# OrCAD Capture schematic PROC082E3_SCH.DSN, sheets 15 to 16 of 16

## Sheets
15 09. FPD LINK_CAM/RDR_IN2: size C; title: FPD Link Camera/RADAR Input2
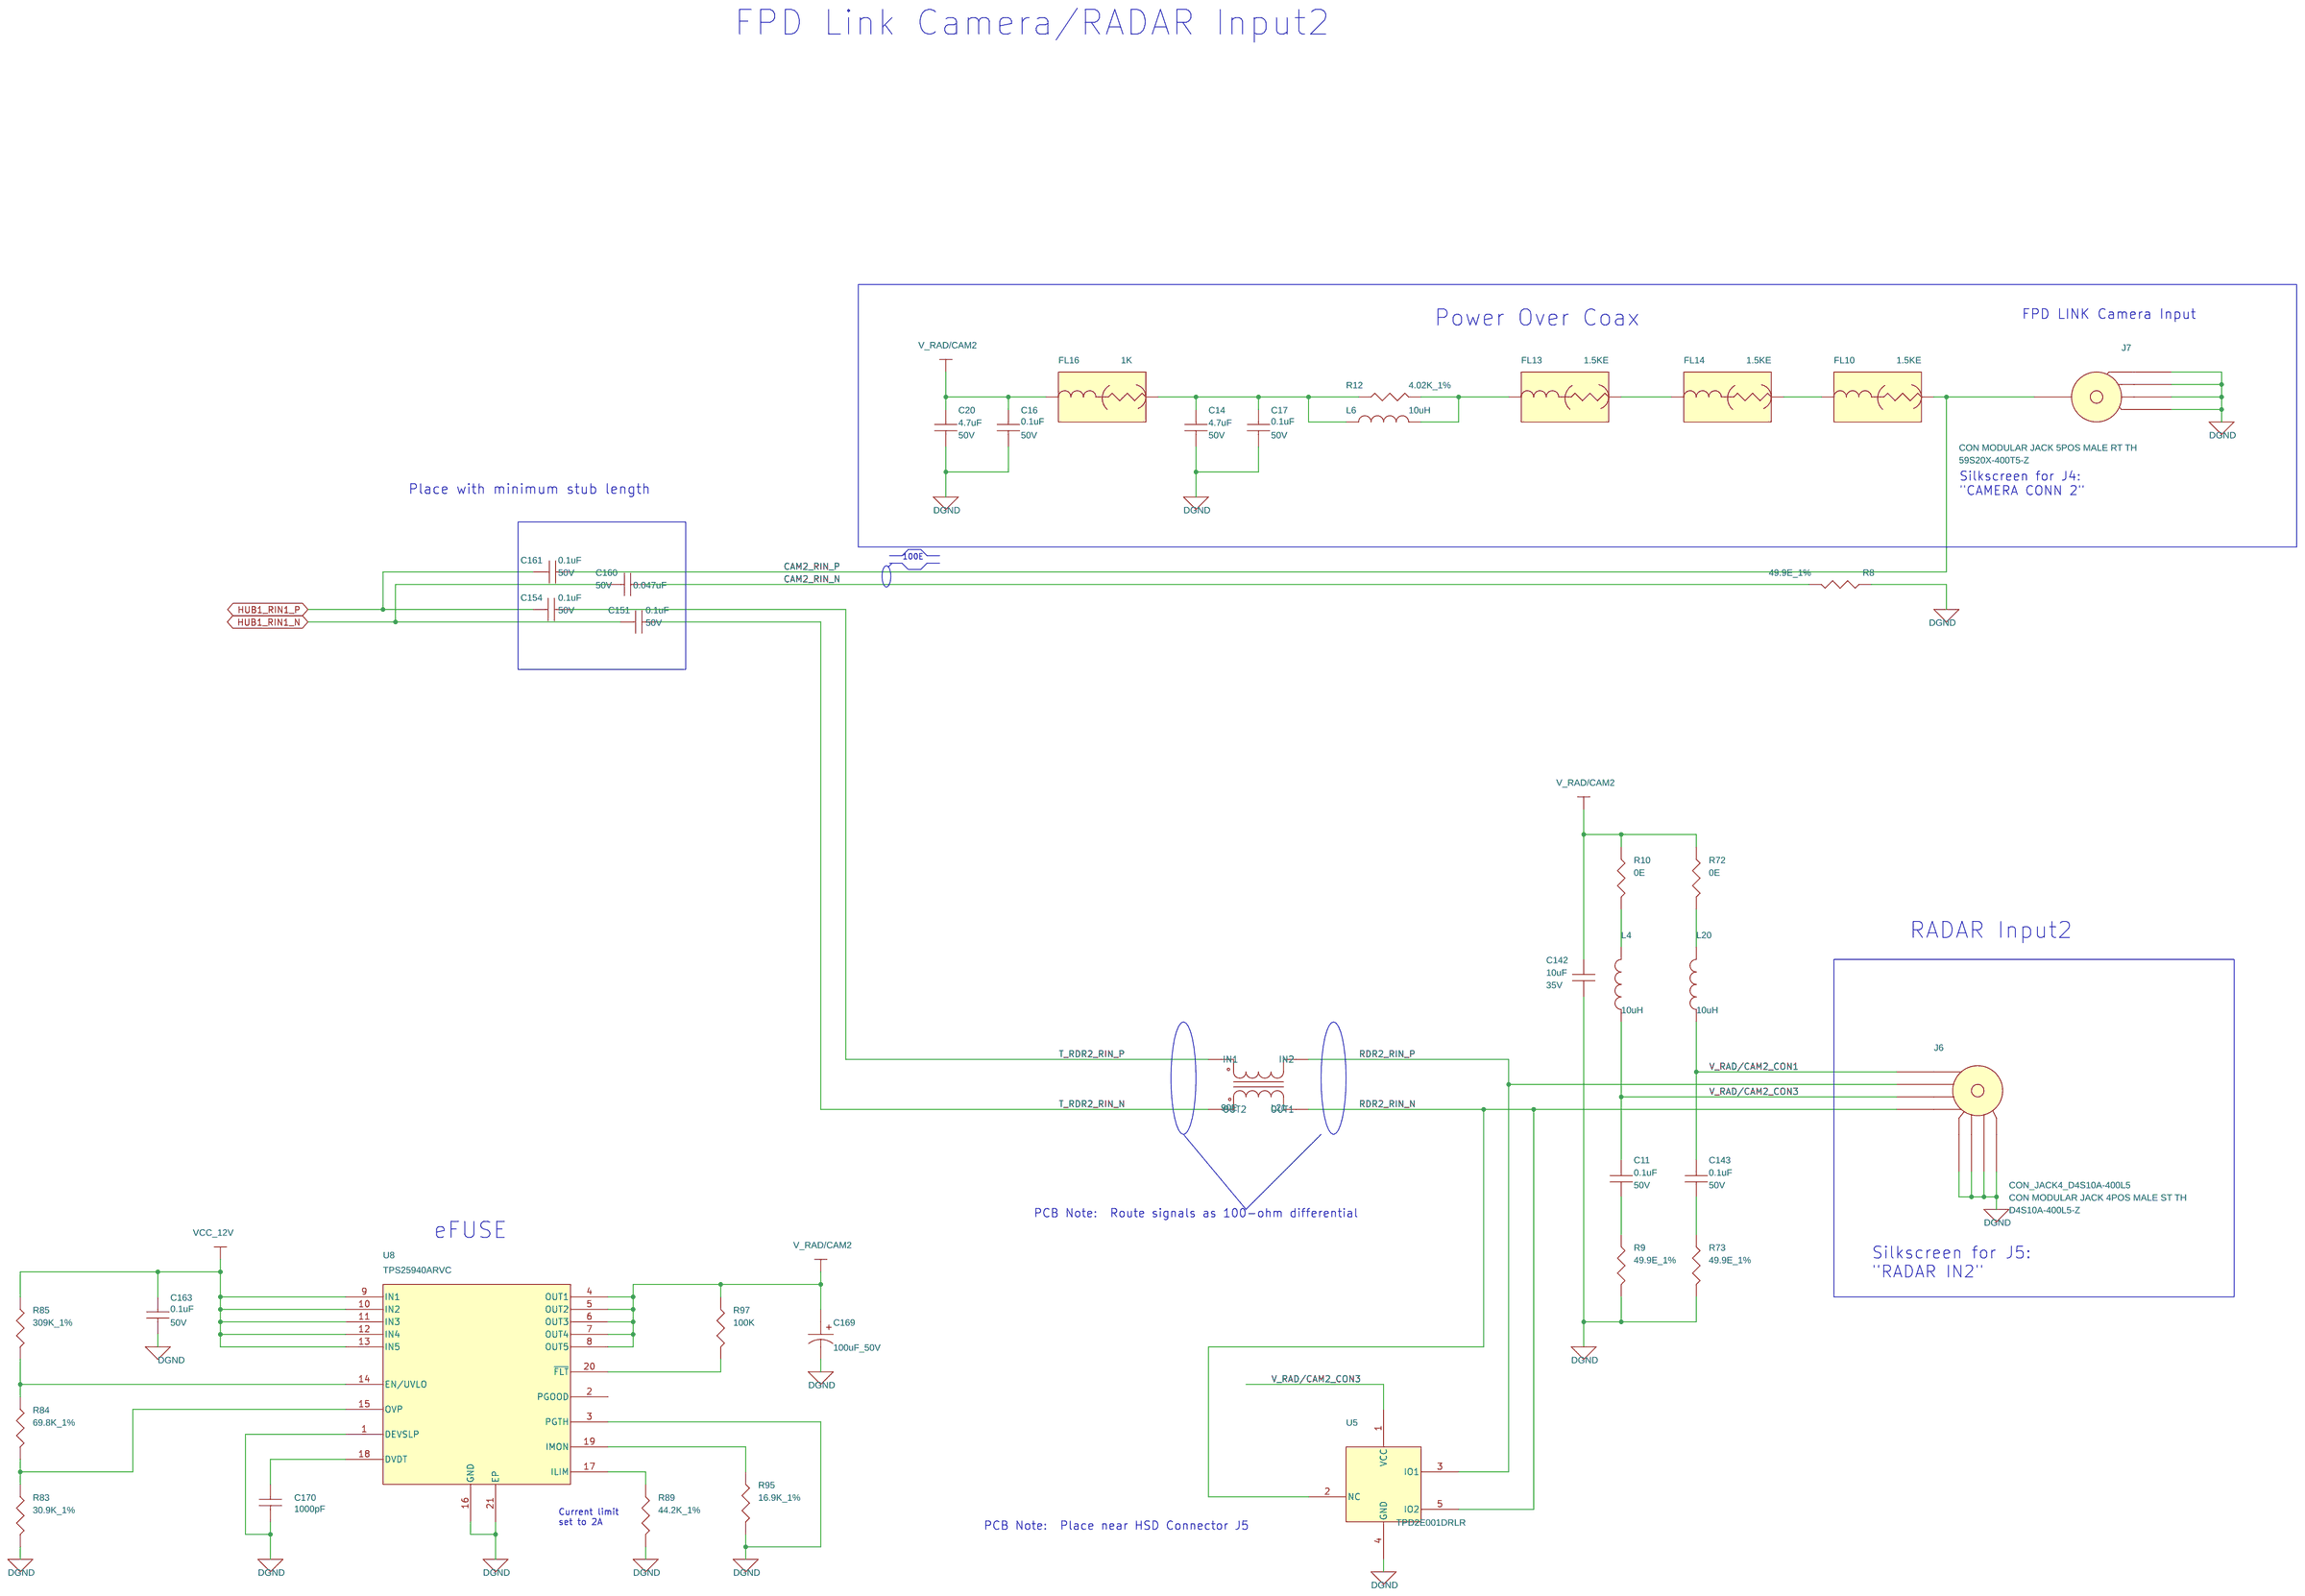
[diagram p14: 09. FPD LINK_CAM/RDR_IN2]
16 11. FPD LINK_CAM/RDR_IN4: size C; title: FPD Link Camera/RADAR Input4
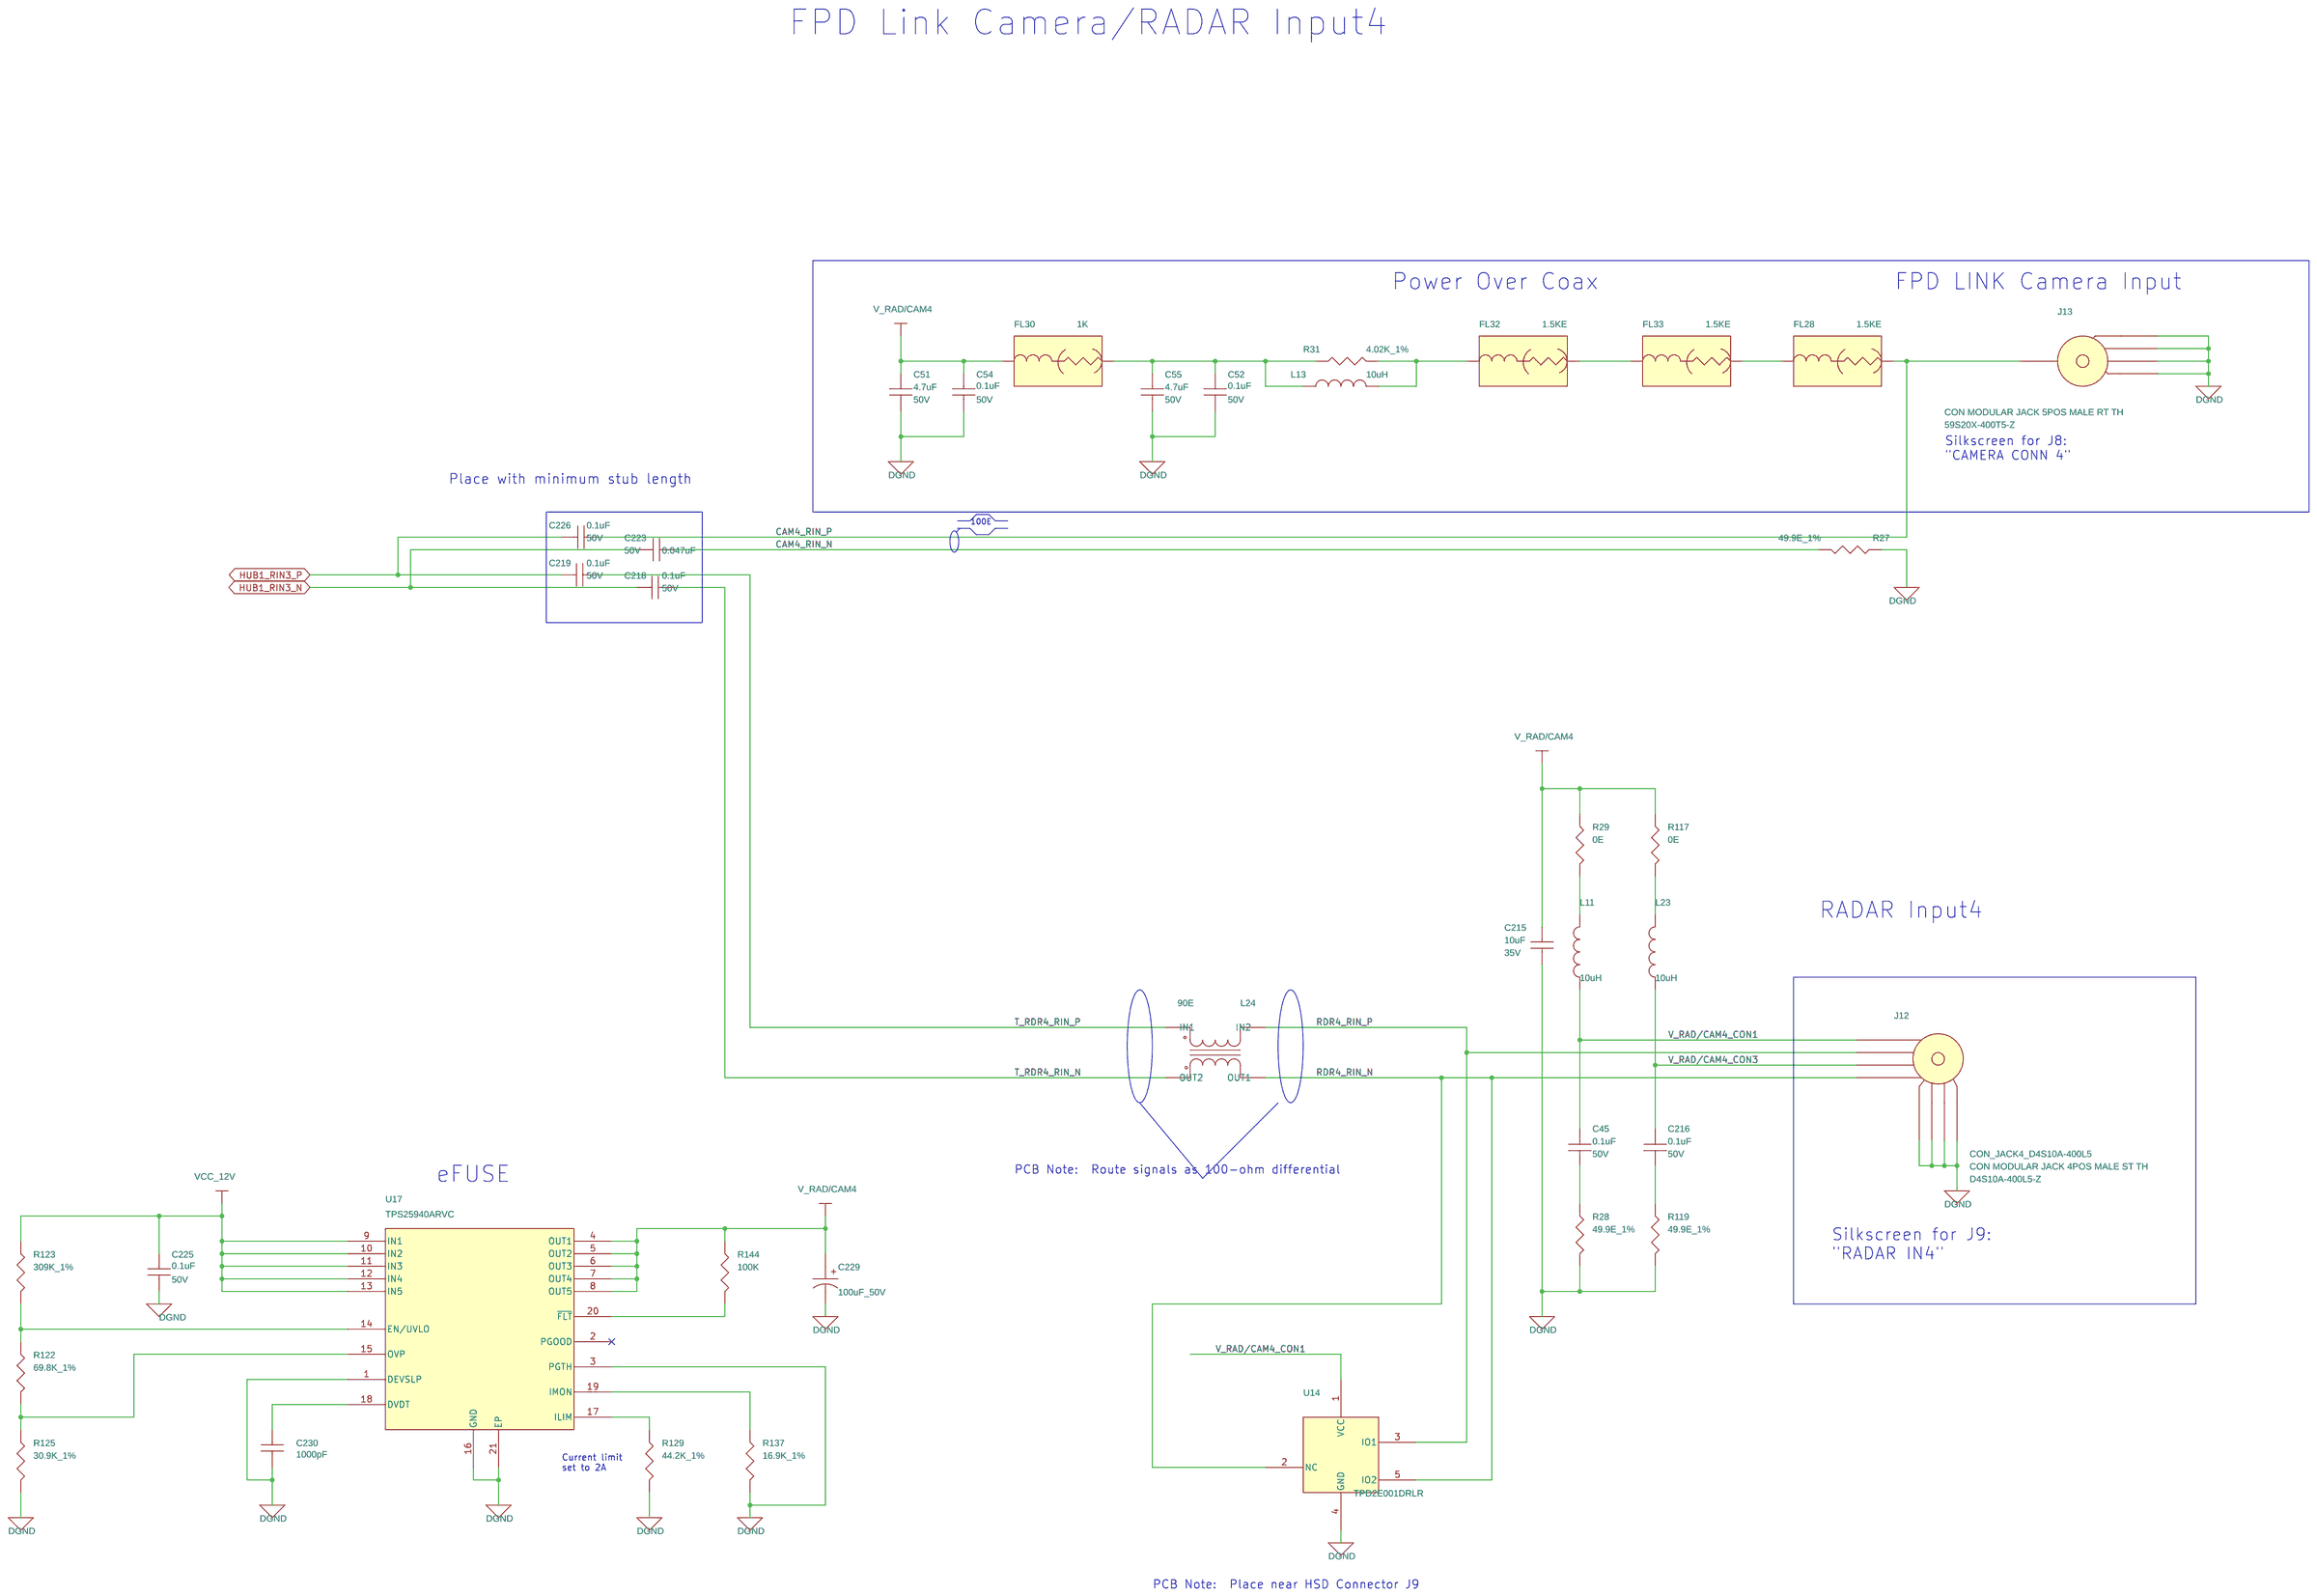
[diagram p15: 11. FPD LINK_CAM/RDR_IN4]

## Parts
sheet 09. FPD LINK_CAM/RDR_IN2
C11  0.1uF  [CAP0402_0-75]
C14  4.7uF  [CAP1206_2]
C16  0.1uF  [CAP0402_0-75]
C17  0.1uF  [CAP0402_0-75]
C20  4.7uF  [CAP1206_2]
C142  10uF  [CAP1206_1]
C143  0.1uF  [CAP0402_0-75]
C151  0.1uF  [CAP0402_0-75]
C154  0.1uF  [CAP0402_0-75]
C160  0.047uF  [CAP0402_0-75]
C161  0.1uF  [CAP0402_0-75]
C163  0.1uF  [CAP0402_0-75]
C169  100uF_50V  [CAPAE_D8CASE_8]
C170  1000pF  [CAP0402_0-75]
FL10  1.5KE  [EMIFIL_BLM18R_0603]
FL13  1.5KE  [EMIFIL_BLM18R_0603]
FL14  1.5KE  [EMIFIL_BLM18R_0603]
FL16  1K  [EMIFIL_BLM18A_0603_1]
J6  CON_JACK4_D4S10A-400L5  [CON_JACK4_D4S10A-400L5-Z_P_S_T_15-4]
J7  CON_JACK5_59S20X-400T5  [CON_JACK5_59S20X-400T5-Z_P_R_T_10-1]
L4  10uH  [IND_MLZ2012N_90X60_SMD]
L6  10uH  [IND_MLZ2012N_90X60_SMD]
L20  10uH  [IND_MLZ2012N_90X60_SMD]
L21  90E  [IND4_DLW21H_90X60_SMD_1-4]
R8  49.9E_1%  [RES0402_0-5]
R9  49.9E_1%  [RES0402_0-5]
R10  0E  [RES0603_0-5]
R12  4.02K_1%  [RES0603_0-5]
R72  0E  [RES0603_0-5]
R73  49.9E_1%  [RES0402_0-5]
R83  30.9K_1%  [RES0402_0-5]
R84  69.8K_1%  [RES0402_0-5]
R85  309K_1%  [RES0402_0-5]
R89  44.2K_1%  [RES0402_0-5]
R95  16.9K_1%  [RES0402_0-5]
R97  100K  [RES0402_0-5]
U5  TPD2E001DRLR  [SOT553-5_0-6]
U8  TPS25940ARVC  [QFN20_19-68_120X160_0-8]
sheet 11. FPD LINK_CAM/RDR_IN4
C45  0.1uF  [CAP0402_0-75]
C51  4.7uF  [CAP1206_2]
C52  0.1uF  [CAP0402_0-75]
C54  0.1uF  [CAP0402_0-75]
C55  4.7uF  [CAP1206_2]
C215  10uF  [CAP1206_1]
C216  0.1uF  [CAP0402_0-75]
C218  0.1uF  [CAP0402_0-75]
C219  0.1uF  [CAP0402_0-75]
C223  0.047uF  [CAP0402_0-75]
C225  0.1uF  [CAP0402_0-75]
C226  0.1uF  [CAP0402_0-75]
C229  100uF_50V  [CAPAE_D8CASE_8]
C230  1000pF  [CAP0402_0-75]
FL28  1.5KE  [EMIFIL_BLM18R_0603]
FL30  1K  [EMIFIL_BLM18A_0603_1]
FL32  1.5KE  [EMIFIL_BLM18R_0603]
FL33  1.5KE  [EMIFIL_BLM18R_0603]
J12  CON_JACK4_D4S10A-400L5  [CON_JACK4_D4S10A-400L5-Z_P_S_T_15-4]
J13  CON_JACK5_59S20X-400T5  [CON_JACK5_59S20X-400T5-Z_P_R_T_10-1]
L11  10uH  [IND_MLZ2012N_90X60_SMD]
L13  10uH  [IND_MLZ2012N_90X60_SMD]
L23  10uH  [IND_MLZ2012N_90X60_SMD]
L24  90E  [IND4_DLW21H_90X60_SMD_1-4]
R27  49.9E_1%  [RES0402_0-5]
R28  49.9E_1%  [RES0402_0-5]
R29  0E  [RES0603_0-5]
R31  4.02K_1%  [RES0603_0-5]
R117  0E  [RES0603_0-5]
R119  49.9E_1%  [RES0402_0-5]
R122  69.8K_1%  [RES0402_0-5]
R123  309K_1%  [RES0402_0-5]
R125  30.9K_1%  [RES0402_0-5]
R129  44.2K_1%  [RES0402_0-5]
R137  16.9K_1%  [RES0402_0-5]
R144  100K  [RES0402_0-5]
U14  TPD2E001DRLR  [SOT553-5_0-6]
U17  TPS25940ARVC  [QFN20_19-68_120X160_0-8]

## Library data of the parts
C11 C16 C17 C45 C52 C54 C143 C151 C154 C161 C163 C216 C218 C219 C225 C226 = CAP: CAP CERAMIC 0.1uF 50V 10% X7R 0402; Chkd/date: MANIRAJA/131217; Crtd /date: ALVY/131217; Custom_Duty: 15%; Customs_HS_Code: 85322990; Distributor_name: DIGIKEY; Distributor_part_number: 478-10043-1-ND; Footprint Path: Y:\MIS_DATABASE\Library\ALTIUM_TOOL\PCB_FOOTPRINTS\Altium_Footprint_Lib.PcbLib; Height: 0.56MM; Library Path: Y:\MIS_DATABASE\Library\ALTIUM_TOOL\SCHEMATICS_PARTS\MS_DISCRETE_Library.schlib; Mfr_name: AVX CORPORATION; Mfr_part_number: 04025C104KAT2A; Mistral Part No: 120011100014-R; Package: 0402; Part_type: CAPACITORS\CERAMIC; Project: ASL_LIU_TYPE-II; RoHS: RoHS; Temperature: -55°C+125°C; Tolerance: 10%; Voltage: 50V; Wattage: NA; Weight: 0.65mg; Datasheet: Y:\MIS_DATABASE\DATASHEETS\CAPACITORS\AVX_MLC.PDF
C14 C20 C51 C55 = CAP: CAP CERAMIC 4.7uF 50V 10% X7R 1206; Chkd/date: VASANTHA/100315; Crtd /date: NAVEED/240714; Custom_Duty: 15%; Customs_HS_Code: 85322990; Distributor_name: DIGIKEY; Distributor_part_number: 587-2994-1-ND; Footprint Path: Y:\MIS_DATABASE\Library\ALTIUM_TOOL\PCB_FOOTPRINTS\Altium_Footprint_Lib.PcbLib; Height: 1.80MM; Library Path: Y:\MIS_DATABASE\Library\ALTIUM_TOOL\SCHEMATICS_PARTS\MS_DISCRETE_Library.schlib; Mfr_name: TAIYO YUDEN; Mfr_part_number: UMK316AB7475KL-T; Mistral Part No: 120014070019-R; Package: 1206; Part_type: CAPACITORS\CERAMIC; Project: MS_ADE_PSM_PSU; RoHS: RoHS; Temperature: -55°C+125°C; Tolerance: 10%; Voltage: 50V; Wattage: NA; Weight: 16.2mg; Datasheet: Y:\MIS_DATABASE\DATASHEETS\CAPACITORS\UMK316AB7475KL-T.PDF
C142 C215 = CAP: CAP CERAMIC 10uF 35V 10% X5R 1206; Chkd/date: MANIRAJA/130618; Crtd /date: MANIRAJA/130618; Custom_Duty: 15%; Customs_HS_Code: 85322990; Distributor_name: DIGIKEY; Distributor_part_number: 490-9964-1-ND; Footprint Path: Y:\MIS_DATABASE\Library\ALTIUM_TOOL\PCB_FOOTPRINTS\Altium_Footprint_Lib.PcbLib; Height: 0.95MM; Library Path: Y:\MIS_DATABASE\Library\ALTIUM_TOOL\SCHEMATICS_PARTS\MS_DISCRETE_Library.schlib; Mfr_name: MURATA; Mfr_part_number: GRM319R6YA106KA12D; Mistral Part No: 120018060022-R; Package: 1206; Part_type: CAPACITORS\CERAMIC; Project: MYTHIC_PCIE_DB; RoHS: RoHS; Temperature: -55°C+85°C; Tolerance: 10%; Voltage: 35V; Wattage: NA; Weight: 40mg; Datasheet: Y:\MIS_DATABASE\DATASHEETS\CAPACITORS\GRM319R6YA106KA12D.PDF
C160 C223 = CAP: CAP CERAMIC 0.047uF 50V 10% X7R 0402; Chkd/date: MANIRAJA/240118; Crtd /date: MANIRAJA/240118; Custom_Duty: 15%; Customs_HS_Code: 85322990; Distributor_name: DIGIKEY; Distributor_part_number: GRM155R71H473KE14J-ND; Footprint Path: Y:\MIS_DATABASE\Library\ALTIUM_TOOL\PCB_FOOTPRINTS\Altium_Footprint_Lib.PcbLib; Height: 0.55MM; Library Path: Y:\MIS_DATABASE\Library\ALTIUM_TOOL\SCHEMATICS_PARTS\MS_DISCRETE_Library.schlib; Mfr_name: MURATA; Mfr_part_number: GRM155R71H473KE14J; Mistral Part No: 120018010011-R; Package: 0402; Part_type: CAPACITORS\CERAMIC; Project: TI_MAXIE_CPB; RoHS: RoHS; Temperature: -55°C+125°C; Tolerance: 10%; Voltage: 50V; Wattage: NA; Weight: 6mg; Datasheet: Y:\MIS_DATABASE\DATASHEETS\CAPACITORS\GRM155R71H473KE14.PDF
C169 C229 = CAP_POL: CAP ELECTROLYTIC 100uF 50V 20% D8CASE_6666; Chkd/date: MANIRAJA/051018; Crtd /date: ALVY/051018; Custom_Duty: 15%; Customs_HS_Code: 85322990; Distributor_name: DIGIKEY; Distributor_part_number: PCE5024CT-ND; Footprint Path: Y:\MIS_DATABASE\Library\ALTIUM_TOOL\PCB_FOOTPRINTS\Altium_Footprint_Lib.PcbLib; Height: 8.00MM; Library Path: Y:\MIS_DATABASE\Library\ALTIUM_TOOL\SCHEMATICS_PARTS\MS_DISCRETE_Library.schlib; Mfr_name: PANASONIC-ECG; Mfr_part_number: EEE-FTH101XAP; Mistral Part No: 120018100013-R; Package: D8CASE_6666; Part_type: CAPACITORS\ELECTROLYTIC; Project: TI_J7_SVB-DUT; RoHS: RoHS; Temperature: -55°C+105°C; Tolerance: 20%; Voltage: 50V; Wattage: NA; Weight: 440mg; Datasheet: Y:\MIS_DATABASE\DATASHEETS\CAPACITORS\FTV-SER.PDF
C170 C230 = CAP: CAP CERAMIC 1000pF 50V 5% C0G(NP0) 0402; Chkd/date: VASANTHA/281216; Crtd /date: MAZHAR/290806; Custom_Duty: 15%; Customs_HS_Code: 85322990; Distributor_name: DIGIKEY; Distributor_part_number: 490-3244-1-ND; Footprint Path: Y:\MIS_DATABASE\Library\ALTIUM_TOOL\PCB_FOOTPRINTS\Altium_Footprint_Lib.PcbLib; Height: 0.55MM; Library Path: Y:\MIS_DATABASE\Library\ALTIUM_TOOL\SCHEMATICS_PARTS\MS_DISCRETE_Library.schlib; Mfr_name: MURATA; Mfr_part_number: GRM1555C1H102JA01D; Mistral Part No: 120016110009-R; Package: 0402; Part_type: CAPACITORS\CERAMIC; Project: SVDO_RMB_MMA; RoHS: RoHS; Temperature: -55°C+125°C; Tolerance: 5%; Voltage: 50V; Wattage: NA; Weight: 6mg; Datasheet: Y:\MIS_DATABASE\DATASHEETS\CAPACITORS\MURATA-GXX-SER_NOV17.PDF
FL10 FL13 FL14 FL28 FL32 FL33 = EMIFILTER_IND: FERRITE BEAD 1.5KE 500MA 0603; Chkd/date: RAGESH/111010; Crtd /date: MUDDU/050210; Custom_Duty: 24%; Customs_HS_Code: 85437099; Distributor_name: DIGIKEY; Distributor_part_number: 490-5216-1-ND; Footprint Path: Y:\MIS_DATABASE\Library\ALTIUM_TOOL\PCB_FOOTPRINTS\Altium_Footprint_Lib.PcbLib; Height: 0.95MM; Library Path: Y:\MIS_DATABASE\Library\ALTIUM_TOOL\SCHEMATICS_PARTS\MS_FILTER_Library.schlib; Mfr_name: MURATA; Mfr_part_number: BLM18HE152SN1; Mistral Part No: 130010020011; Package: 0603; Part_type: FILTER; Project: NPOL_CONTROLLERCARD; Temperature: -55°C+125°C; Tolerance: NA; Voltage: NA; Wattage: NA; Weight: NA; Datasheet: Y:\MIS_DATABASE\DATASHEETS\DISCRETES\INDUCTORS\BLM18H.PDF
FL16 FL30 = EMIFILTER_IND: IND FERRITE BEAD CHIP 1K 450mA 0603; Chkd/date: MANIRAJA/070818; Crtd /date: USMAN/070409; Custom_Duty: 24%; Customs_HS_Code: 85437099; Distributor_name: DIGIKEY; Distributor_part_number: 490-1015-1-ND; Footprint Path: Y:\MIS_DATABASE\Library\ALTIUM_TOOL\PCB_FOOTPRINTS\Altium_Footprint_Lib.PcbLib; Height: 0.95MM; Library Path: Y:\MIS_DATABASE\Library\ALTIUM_TOOL\SCHEMATICS_PARTS\MS_DISCRETE_Library.schlib; Mfr_name: MURATA; Mfr_part_number: BLM18AG102SN1D; Mistral Part No: 130009070006-R; Package: 0603; Part_type: INDUCTOR; Project: AARDK; RoHS: RoHS; Temperature: -55°C+125°C; Tolerance: 25%; Voltage: NA; Wattage: NA; Weight: 5mg; Datasheet: Y:\MIS_DATABASE\DATASHEETS\DISCRETES\INDUCTORS\BLM18A-N1.PDF
J6 J12 = CON_JACK4_EXG.0B.304: CON MODULAR JACK 4POS MALE ST TH; Chkd/date: MANIRAJA/251018; Crtd /date: ALVY/251018; Custom_Duty: 24%; Customs_HS_Code: 85369090; Distributor_name: DIGIKEY; Distributor_part_number: D4S10A-400L5-Z-ND; Footprint Path: Y:\MIS_DATABASE\Library\ALTIUM_TOOL\PCB_FOOTPRINTS\Altium_Footprint_Lib.PcbLib; Height: 15.40MM; Library Path: Y:\MIS_DATABASE\Library\ALTIUM_TOOL\SCHEMATICS_PARTS\MS_CONNECTOR_Library.schlib; Mfr_name: ROSENBERGER; Mfr_part_number: D4S10A-400L5-Z; Mistral Part No: 150018100044-R; Package: THRU-HOLE; Part_type: CONNECTOR\JACK; Project: TI_J7ES_EVM_FUSION2_SER_CAP; RoHS: RoHS; Temperature: -40°C+105°C; Tolerance: NA; Voltage: NA; Wattage: NA; Weight: 2900mg; Datasheet: Y:\MIS_DATABASE\DATASHEETS\CONNECTORS\D4S10A-400L5-Y.PDF
J7 J13 = CON5_MCXJACK_TH: CON MODULAR JACK 5POS MALE RT TH; Chkd/date: MANIRAJA/020519; Crtd /date: MANIRAJA/020519; Custom_Duty: 24%; Customs_HS_Code: 85369090; Distributor_name: NA; Distributor_part_number: NA; Footprint Path: Y:\MIS_DATABASE\Library\ALTIUM_TOOL\PCB_FOOTPRINTS\Altium_Footprint_Lib.PcbLib; Height: 10.05MM; Library Path: Y:\MIS_DATABASE\Library\ALTIUM_TOOL\SCHEMATICS_PARTS\MS_CONNECTOR_Library.schlib; Mfr_name: ROSENBERGER; Mfr_part_number: 59S20X-400T5-Z; Mistral Part No: 150019050002-R; Package: THRU-HOLE; Part_type: CONNECTOR\JACK; Project: TI_J7ES_EVM_FUSION2_SER_CAP; RoHS: RoHS; Temperature: -40°C+105°C; Tolerance: NA; Voltage: NA; Wattage: NA; Weight: 3880mg; Datasheet: Y:\MIS_DATABASE\DATASHEETS\CONNECTORS\59S20X-400T5-Y.PDF
L4 L6 L11 L13 L20 L23 = INDUCTOR: IND 10uH 20% 500mA SMD; Alternate_mfr_name_A: TDK CORPORATION; Alternate_mfr_part_number_A: MLZ2012N100LT000; Chkd/date: BALACHANDAR/150514; Crtd /date: SARANYA/120514; Custom_Duty: 24%; Customs_HS_Code: 85437099; Distributor_name: MOUSER; Distributor_name_A: DIGIKEY; Distributor_part_number: 810-MLZ2012N100L; Distributor_part_number_A: 445-6762-1-ND; Height: 1.25MM; Mfr_name: TDK CORPORATION; Mfr_part_number: MLZ2012N100L; Mistral Part No: 130014050064-R; Package: 0805; Project: AEGIS GP BETA2; RoHS: RoHS; Temperature: -55°C+125°C; Tolerance: NA; Voltage: NA; Wattage: NA; Weight: 14mg; Datasheet: Y:\MIS_DATABASE\DATASHEETS\DISCRETES\INDUCTORS\MLZ2012_SERIES.PDF
L21 L24 = INDUCTOR_DLW31S: IND COMMON MODE CHOKE 90E 280mA SMD; Chkd/date: MANIRAJA/270619; Crtd /date: MANIRAJA/270619; Custom_Duty: 24%; Customs_HS_Code: 85437099; Distributor_name: NA; Distributor_part_number: NA; Footprint Path: Y:\MIS_DATABASE\Library\ALTIUM_TOOL\PCB_FOOTPRINTS\Altium_Footprint_Lib.PcbLib; Height: 1.40MM; Library Path: Y:\MIS_DATABASE\Library\ALTIUM_TOOL\SCHEMATICS_PARTS\MS_DISCRETE_Library.schlib; Mfr_name: MURATA; Mfr_part_number: DLW21SZ900HQ2B; Mistral Part No: 130019060035-R; Package: SMD; Part_type: INDUCTOR; Project: TI_J7ES_CP; RoHS: RoHS; Temperature: -40°C+105°C; Tolerance: NA; Voltage: NA; Wattage: NA; Weight: 11mg; Datasheet: Y:\MIS_DATABASE\DATASHEETS\DISCRETES\INDUCTORS\DLW21SZ900HQ2B.PDF
R8 R9 R27 R28 R73 R119 = RESISTOR: RES 49.9E 1/10W 1% 0402; Chkd/date: VASANTHA/201216; Crtd /date: MAZHAR/201005; Custom_Duty: 15%; Customs_HS_Code: 85332119; Distributor_name: DIGIKEY; Distributor_part_number: P49.9LCT-ND; Footprint Path: Y:\MIS_DATABASE\Library\ALTIUM_TOOL\PCB_FOOTPRINTS\Altium_Footprint_Lib.PcbLib; Height: 0.40MM; Library Path: Y:\MIS_DATABASE\Library\ALTIUM_TOOL\SCHEMATICS_PARTS\MS_DISCRETE_Library.schlib; Mfr_name: PANASONIC-ECG; Mfr_part_number: ERJ-2RKF49R9X; Mistral Part No: 110009030897-R; Package: 0402; Part_type: RESISTORS\FIXED; Project: RED EYE; RoHS: RoHS; Temperature: -55°C+155°C; Tolerance: 1%; Voltage: NA; Wattage: 1/10W; Weight: 0.8mg; Datasheet: Y:\MIS_DATABASE\DATASHEETS\RESISTORS\PAN-ERJSER_NOV17.PDF
R10 R29 R72 R117 = RESISTOR: RES 0E 1/10W JUMPER 0603; Chkd/date: MANIRAJA/220618; Crtd /date: MUDDU/120310; Custom_Duty: 15%; Customs_HS_Code: 85332119; Distributor_name: DIGIKEY; Distributor_part_number: 541-2968-1-ND; Footprint Path: Y:\MIS_DATABASE\Library\ALTIUM_TOOL\PCB_FOOTPRINTS\Altium_Footprint_Lib.PcbLib; Height: 0.50MM; Library Path: Y:\MIS_DATABASE\Library\ALTIUM_TOOL\SCHEMATICS_PARTS\MS_DISCRETE_Library.schlib; Mfr_name: VISHAY; Mfr_part_number: CRCW06030000Z0EB; Mistral Part No: 110010030044-R; Package: 0603; Part_type: RESISTORS\FIXED; Project: BLR-3 PSPU; RoHS: RoHS; Temperature: -55°C+155°C; Tolerance: NA; Voltage: NA; Wattage: 1/10W; Weight: 2mg; Datasheet: Y:\MIS_DATABASE\DATASHEETS\RESISTORS\CRCW0603.PDF
R12 R31 = RESISTOR: RES 4.02K 1/10W 1% 0603; Chkd/date: VASANTHA/201216; Crtd /date: MAZHAR/241109; Custom_Duty: 15%; Customs_HS_Code: 85332119; Distributor_name: DIGIKEY; Distributor_part_number: 541-4.02KHCT-ND; Footprint Path: Y:\MIS_DATABASE\Library\ALTIUM_TOOL\PCB_FOOTPRINTS\Altium_Footprint_Lib.PcbLib; Height: 0.50MM; Library Path: Y:\MIS_DATABASE\Library\ALTIUM_TOOL\SCHEMATICS_PARTS\MS_DISCRETE_Library.schlib; Mfr_name: VISHAY; Mfr_part_number: CRCW06034K02FKEA; Mistral Part No: 110009110009-R; Package: 0603; Part_type: RESISTORS\FIXED; Project: NPOL_FPS; RoHS: RoHS; Temperature: -55°C+155°C; Tolerance: 1%; Voltage: NA; Wattage: 1/10W; Weight: 2mg; Datasheet: Y:\MIS_DATABASE\DATASHEETS\RESISTORS\CRCW0603.PDF
R83 R125 = RESISTOR: RES 30.9K 1/10W 1% 0402; Chkd/date: MAZHAR/080311; Crtd /date: BAVISH/230211; Custom_Duty: 15%; Customs_HS_Code: 85332119; Distributor_name: DIGIKEY; Distributor_part_number: P30.9KLCT-ND; Footprint Path: Y:\MIS_DATABASE\Library\ALTIUM_TOOL\PCB_FOOTPRINTS\Altium_Footprint_Lib.PcbLib; Height: 0.40MM; Library Path: Y:\MIS_DATABASE\Library\ALTIUM_TOOL\SCHEMATICS_PARTS\MS_DISCRETE_Library.schlib; Mfr_name: PANASONIC-ECG; Mfr_part_number: ERJ-2RKF3092X; Mistral Part No: 110011020022-R; Package: 0402; Part_type: RESISTORS\FIXED; Project: GOLDEN-I; RoHS: RoHS; Temperature: -55°C+155°C; Tolerance: 1%; Voltage: NA; Wattage: 1/10W; Weight: 0.8mg; Datasheet: Y:\MIS_DATABASE\DATASHEETS\RESISTORS\PAN-ERJSER_NOV17.PDF
R84 R122 = RESISTOR: RES 69.8K 1/10W 1% 0402; Chkd/date: SHREESHAIL/121205; Crtd /date: MAZHAR/030605; Custom_Duty: 15%; Customs_HS_Code: 85332119; Distributor_name: DIGIKEY; Distributor_part_number: P69.8KLCT-ND; Footprint Path: Y:\MIS_DATABASE\Library\ALTIUM_TOOL\PCB_FOOTPRINTS\Altium_Footprint_Lib.PcbLib; Height: 0.40MM; Library Path: Y:\MIS_DATABASE\Library\ALTIUM_TOOL\SCHEMATICS_PARTS\MS_DISCRETE_Library.schlib; Mfr_name: PANASONIC-ECG; Mfr_part_number: ERJ-2RKF6982X; Mistral Part No: 110009031082-R; Package: 0402; Part_type: RESISTORS\FIXED; Project: G4SLIM; RoHS: RoHS; Temperature: -55°C+155°C; Tolerance: 1%; Voltage: NA; Wattage: 1/10W; Weight: 0.8mg; Datasheet: Y:\MIS_DATABASE\DATASHEETS\RESISTORS\PAN-ERJSER_NOV17.PDF
R85 R123 = RESISTOR: RES 309K 1/10W 1% 0402; Chkd/date: JEBRAN/060215; Crtd /date: USMAN/140313; Custom_Duty: 15%; Customs_HS_Code: 85332119; Distributor_name: DIGIKEY; Distributor_part_number: P309KLCT-ND; Footprint Path: Y:\MIS_DATABASE\Library\ALTIUM_TOOL\PCB_FOOTPRINTS\Altium_Footprint_Lib.PcbLib; Height: 0.40MM; Library Path: Y:\MIS_DATABASE\Library\ALTIUM_TOOL\SCHEMATICS_PARTS\MS_DISCRETE_Library.schlib; Mfr_name: PANASONIC-ECG; Mfr_part_number: ERJ-2RKF3093X; Mistral Part No: 110013030008-R; Package: 0402; Part_type: RESISTORS\FIXED; Project: DTRM; RoHS: RoHS; Temperature: -55°C+155°C; Tolerance: 1%; Voltage: NA; Wattage: 1/10W; Weight: 0.8mg; Datasheet: Y:\MIS_DATABASE\DATASHEETS\RESISTORS\PAN-ERJSER_NOV17.PDF
R89 R129 = RESISTOR: RES 44.2K 1/16W 1% 0402; Chkd/date: ALVY/041120; Crtd /date: ALVY/041120; Custom_Duty: 15%; Customs_HS_Code: 85332119; Distributor_name: DIGIKEY; Distributor_part_number: 541-4106-1-ND; Footprint Path: Y:\MIS_DATABASE\Library\ALTIUM_TOOL\PCB_FOOTPRINTS\Altium_Footprint_Lib.PcbLib; Height: 0.35MM; Library Path: Y:\MIS_DATABASE\Library\ALTIUM_TOOL\SCHEMATICS_PARTS\MS_DISCRETE_Library.schlib; Mfr_name: VISHAY; Mfr_part_number: CRCW040244K2FKEDC; Mistral Part No: 110010070032-R; Package: 0402; Part_type: RESISTORS\FIXED; Project: TI_J7ES_EVM_FUSION2_SER_CAP; RoHS: RoHS; Temperature: -55°C+155°C; Tolerance: 1%; Voltage: NA; Wattage: 1/16W; Weight: 0.65mg; Datasheet: Y:\MIS_DATABASE\DATASHEETS\RESISTORS\CRCW_C-SER.PDF
R95 R137 = RESISTOR: RES 16.9K 1/10W 1% 0402; Chkd/date: SHREESHAIL/24050; Crtd /date: MAZHAR/260706; Custom_Duty: 15%; Customs_HS_Code: 85332119; Distributor_name: DIGIKEY; Distributor_part_number: P16.9KLCT-ND; Footprint Path: Y:\MIS_DATABASE\Library\ALTIUM_TOOL\PCB_FOOTPRINTS\Altium_Footprint_Lib.PcbLib; Height: 0.40MM; Library Path: Y:\MIS_DATABASE\Library\ALTIUM_TOOL\SCHEMATICS_PARTS\MS_DISCRETE_Library.schlib; Mfr_name: PANASONIC-ECG; Mfr_part_number: ERJ-2RKF1692X; Mistral Part No: 110009030351-R; Package: 0402; Part_type: RESISTORS\FIXED; Project: POWERBOX; RoHS: RoHS; Temperature: -55°C+155°C; Tolerance: 1%; Voltage: NA; Wattage: 1/10W; Weight: 0.8mg; Datasheet: Y:\MIS_DATABASE\DATASHEETS\RESISTORS\PAN-ERJSER_NOV17.PDF
R97 R144 = RESISTOR: RES 100K 1/16W 5% 0402; Chkd/date: VASANTHA/061216; Crtd /date: BAVISH/010611; Custom_Duty: 15%; Customs_HS_Code: 85332119; Distributor_name: DIGIKEY; Distributor_part_number: 541-100KJCT-ND; Footprint Path: Y:\MIS_DATABASE\Library\ALTIUM_TOOL\PCB_FOOTPRINTS\Altium_Footprint_Lib.PcbLib; Height: 0.40MM; Library Path: Y:\MIS_DATABASE\Library\ALTIUM_TOOL\SCHEMATICS_PARTS\MS_DISCRETE_Library.schlib; Mfr_name: VISHAY; Mfr_part_number: CRCW0402100KJNED; Mistral Part No: 110011060002-R; Package: 0402; Part_type: RESISTORS\FIXED; Project: AM4515_EVM_LCD; RoHS: RoHS; Temperature: -55°C+155°C; Tolerance: 5%; Voltage: NA; Wattage: 1/16W; Weight: 0.65mg; Datasheet: Y:\MIS_DATABASE\DATASHEETS\RESISTORS\CRCW0603.PDF
U5 U14 = TPD2E001DRLR_SOT-5: IC ESD-PROTECTION DIODE ARRAYS SOT-5; Chkd/date: NAVEED/150714; Crtd /date: MUDDU/250510; Custom_Duty: 15%; Customs_HS_Code: 85423100; Distributor_name: DIGIKEY; Distributor_part_number: 296-21883-1-ND; Footprint Path: Y:\MIS_DATABASE\Library\ALTIUM_TOOL\PCB_FOOTPRINTS\Altium_Footprint_Lib.PcbLib; Height: 0.60MM; Library Path: Y:\MIS_DATABASE\Library\ALTIUM_TOOL\SCHEMATICS_PARTS\MS_FILTER_Library.schlib; Mfr_name: TEXAS INSTRUMENTS; Mistral Part No: 140110060007-R; Package: SOT-5; Part_type: ICS\ANALOG\ACTIVE FILTER; Project: CENTAURUS; RoHS: RoHS; Temperature: -40°C+85°C; Tolerance: NA; Voltage: NA; Wattage: NA; Weight: 2.8mg; Datasheet: Y:\MIS_DATABASE\DATASHEETS\ICS\MISC\TPD2E001DRLR.PDF
U8 U17 = TPS25940_WQFN20_TI: IC eFUSE WITH TRUE REVERSE BLOCKING AND DEVSLEEP SUPPORT FOR SSD WQFN20; Chkd/date: MANIRAJA/220818; Crtd /date: ALVY/220818; Custom_Duty: 15%; Customs_HS_Code: 85423100; Distributor_name: DIGIKEY; Distributor_part_number: 296-46233-1-ND; Footprint Path: Y:\MIS_DATABASE\Library\ALTIUM_TOOL\PCB_FOOTPRINTS\Altium_Footprint_Lib.PcbLib; Height: 0.80MM; Library Path: Y:\MIS_DATABASE\Library\ALTIUM_TOOL\SCHEMATICS_PARTS\MS_MISCPOWER_Library.schlib; Library Ref: TPS25940_WQFN20; Mfr_name: TEXAS INSTRUMENTS; Mfr_part_number: TPS25940ARVCR; Mistral Part No: 142018080015-R; Package: WQFN20; Part_type: ICS\POWER\POWER MANAGEMENT; Project: TI_J7ES_EVM_FUSION2_SER_CAP; RoHS: RoHS; Temperature: -40°C+85°C; Tolerance: NA; Voltage: NA; Wattage: NA; Weight: 38.1mg; Datasheet: Y:\MIS_DATABASE\DATASHEETS\ICS\POWER\TPS25940XX.PDF

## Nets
DGND: C14.2 C16.2 C17.2 C20.2 C51.2 C52.2 C54.2 C55.2 C142.2 C163.2 C169.2 C170.2 C215.2 C225.2 C229.2 C230.2 J6.SH1 J6.SH2 J6.SH3 J6.SH4 J7.2 J7.3 J7.4 J7.5 J12.SH1 J12.SH2 J12.SH3 J12.SH4 J13.2 J13.3 J13.4 J13.5 R8.1 R9.2 R27.1 R28.2 R73.2 R83.2 R89.2 R95.2 R119.2 R125.2 R129.2 R137.2 U5.4(GND) U8.1(DEVSLP) U8.3(PGTH) U8.16(GND) U8.21(EP) U14.4(GND) U17.1(DEVSLP) U17.3(PGTH) U17.16(GND) U17.21(EP) ; also on sheet 4 5 6 7 8 9 10 11 13 14
VCC_12V: C163.1 C225.1 R85.1 R123.1 U8.9(IN1) U8.10(IN2) U8.11(IN3) U8.12(IN4) U8.13(IN5) U17.9(IN1) U17.10(IN2) U17.11(IN3) U17.12(IN4) U17.13(IN5) ; also on sheet 8 9 11 13 14
CAM2_RIN_N: C160.1 R8.2
CAM2_RIN_P: C161.1 FL10.2 J7.1
CAM4_RIN_N: C223.1 R27.2
CAM4_RIN_P: C226.1 FL28.2 J13.1
HUB1_RIN1_N: C151.1 C160.2 ; also on sheet 4
HUB1_RIN1_P: C154.1 C161.2 ; also on sheet 4
HUB1_RIN3_N: C218.1 C223.2 ; also on sheet 4
HUB1_RIN3_P: C219.1 C226.2 ; also on sheet 4
RDR2_RIN_N: J6.4 L21.3(OUT1) U5.2(NC) U5.5(IO2)
RDR2_RIN_P: J6.2 L21.2(IN2) U5.3(IO1)
RDR4_RIN_N: J12.4 L24.3(OUT1) U14.2(NC) U14.5(IO2)
RDR4_RIN_P: J12.2 L24.2(IN2) U14.3(IO1)
T_RDR2_RIN_N: C151.2 L21.4(OUT2)
T_RDR2_RIN_P: C154.2 L21.1(IN1)
T_RDR4_RIN_N: C218.2 L24.4(OUT2)
T_RDR4_RIN_P: C219.2 L24.1(IN1)
V_RAD/CAM2: C16.1 C20.1 C142.1 C169.1 FL16.1 R10.1 R72.1 R97.1 U8.4(OUT1) U8.5(OUT2) U8.6(OUT3) U8.7(OUT4) U8.8(OUT5)
V_RAD/CAM2_CON1: C143.2 J6.1 L20.1
V_RAD/CAM2_CON3: C11.2 J6.3 L4.1 U5.1(VCC)
V_RAD/CAM4: C51.1 C54.1 C215.1 C229.1 FL30.1 R29.1 R117.1 R144.1 U17.4(OUT1) U17.5(OUT2) U17.6(OUT3) U17.7(OUT4) U17.8(OUT5)
V_RAD/CAM4_CON1: C45.2 J12.1 L11.1 U14.1(VCC)
V_RAD/CAM4_CON3: C216.2 J12.3 L23.1
N23290514: FL13.1 L6.2 R12.2
N23290520: C14.1 C17.1 FL16.2 L6.1 R12.1
N23290544: FL10.1 FL14.2
N23290557: FL13.2 FL14.1
N23290886: C11.1 R9.1
N23290898: C143.1 R73.1
N23290929: L4.2 R10.2
N23290931: L20.2 R72.2
N23301401: FL32.1 L13.2 R31.2
N23301413: C52.1 C55.1 FL30.2 L13.1 R31.1
N23301427: FL28.1 FL33.2
N23301436: FL32.2 FL33.1
N23301766: C45.1 R28.1
N23301784: C216.1 R119.1
N23301809: L23.2 R117.2
N23301811: L11.2 R29.2
N23315548: R84.1 R85.2 U8.14(EN/UVLO)
N23315552: R83.1 R84.2 U8.15(OVP)
N23315587: C170.1 U8.18(DVDT)
N23315604: R89.1 U8.17(ILIM)
N23315632: R95.1 U8.19(IMON)
N23315748: R97.2 U8.20(~{FLT})
N23317098: R122.1 R123.2 U17.14(EN/UVLO)
N23317110: R122.2 R125.1 U17.15(OVP)
N23317144: C230.1 U17.18(DVDT)
N23317167: R129.1 U17.17(ILIM)
N23317190: R137.1 U17.19(IMON)
N23317306: R144.2 U17.20(~{FLT})

Not connected (* = marked no-connect by the designer): U8 2(PGOOD); U17 2(PGOOD)*

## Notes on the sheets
sheet 15
- FPD Link Camera/RADAR Input2
- Power Over Coax
- FPD LINK Camera Input
- Silkscreen for J4:
  "CAMERA CONN 2"
- Place with minimum stub length
- 100E
- RADAR Input2
- PCB Note:  Route signals as 100-ohm differential
- eFUSE
- Silkscreen for J5:
  "RADAR IN2"
- Current limit
  set to 2A
- PCB Note:  Place near HSD Connector J5
sheet 16
- FPD Link Camera/RADAR Input4
- Power Over Coax
- FPD LINK Camera Input
- Silkscreen for J8:
  "CAMERA CONN 4"
- Place with minimum stub length
- 100E
- RADAR Input4
- eFUSE
- PCB Note:  Route signals as 100-ohm differential
- Silkscreen for J9:
  "RADAR IN4"
- Current limit
  set to 2A
- PCB Note:  Place near HSD Connector J9
